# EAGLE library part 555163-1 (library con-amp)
AMP connector
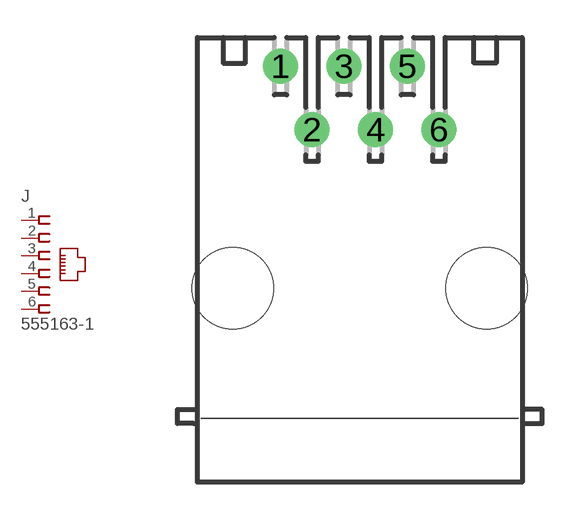
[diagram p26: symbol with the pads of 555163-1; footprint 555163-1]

Designator prefix J

## 555163-1 (MF: TYCO ELECTRONICS; MPN: 5555163-1; OC_FARNELL: 1557717; OC_NEWARK: 42K8759)  [555163-1]
1  1  pas
2  2  pas
3  3  pas
4  4  pas
5  5  pas
6  6  pas

## Footprint 555163-1 (pad centres in mm)
Modular Jack with Panel Stops
drill 0.889 round: 1 -3.175,7.747; 2 -1.905,5.207; 3 -0.635,7.747; 4 0.635,5.207; 5 1.905,7.747; 6 3.175,5.207
hole 3.251 at -5.08,-1.143
hole 3.251 at 5.08,-1.143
